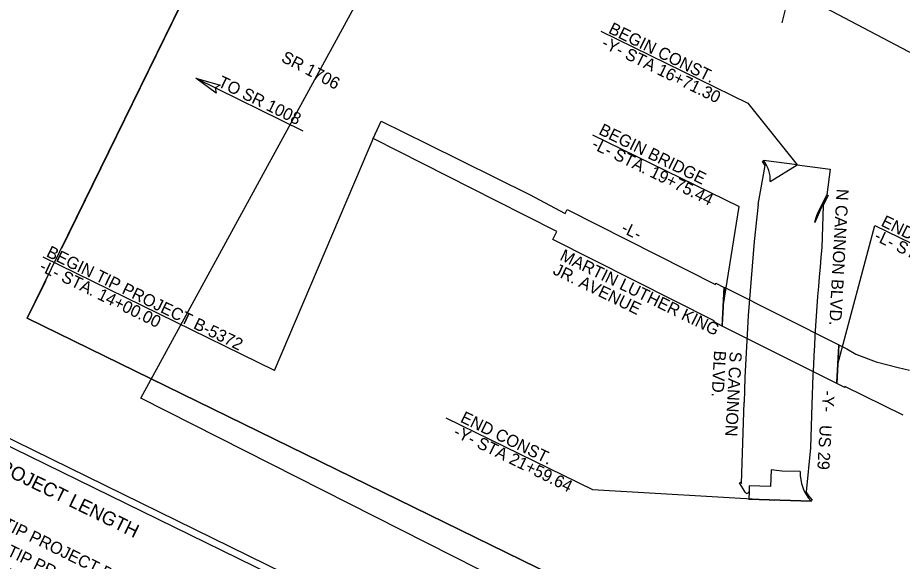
# Model space of a CAD drawing. Extents: x 1517888 to 1526099, y 633375 to 640181.
# Drawn here: x 1519355 to 1520641, y 637793 to 638583 of the extents above; entities that cross this region are included whole.
import ezdxf

# ---------------------------------------------------------------- set-up
doc = ezdxf.new("R2010")
doc.units = 0
for name, color, linetype in [('Prop Shade Heavy', 7, 'Continuous'), ('Prop Shade Light', 7, 'Continuous'), ('Prop Terminator CELL', 7, 'Continuous'), ('Scratch_Level_0', 7, 'Continuous'), ('Sheet Clip Boundary CELL', 7, 'Continuous'), ('Sheet Data Field CELL', 7, 'Continuous'), ('Sheet Title CELL', 7, 'Continuous')]:
    doc.layers.add(name, color=color, linetype=linetype)

msp = doc.modelspace()

# ---------------------------------------------------------------- linework, layer by layer
at = {"layer": 'Prop Shade Heavy'}
msp.add_lwpolyline([(1520545.8, 638051.5), (1520379.2, 638135.1), (1520382.3, 638191.5), (1520548.9, 638107.9)], close=True, dxfattribs=at)
at = {"layer": 'Prop Shade Light'}
for p, q in [((1520437.7, 638374.3), (1520439.3, 638375.5)), ((1520488.1, 638369.2), (1520439.3, 638375.5)), ((1520449.2, 638345), (1520488.1, 638369.2)), ((1520449.2, 638345), (1520488.1, 638369.2)), ((1520488.1, 638369.2), (1520536.2, 638363)), ((1520536.2, 638363), (1520531.4, 638325.7)), ((1520531.4, 638325.7), (1520513.8, 638285.5)), ((1520513.8, 638285.5), (1520531.4, 638325.7)), ((1520517.9, 638298.5), (1520531.4, 638325.7)), ((1520531.4, 638325.7), (1520517.9, 638298.5)), ((1520533.2, 638324.9), (1520525.9, 638310.2)), ((1520531.4, 638325.7), (1520533.2, 638324.9)), ((1520525.9, 638310.2), (1520524.2, 638249.4)), ((1520407.4, 637906.2), (1520411.1, 638024.2)), ((1520450.5, 637926), (1520449.8, 637902.1)), ((1520450.5, 637926), (1520449.8, 637902.1)), ((1520466, 637924.3), (1520450.5, 637926)), ((1520466, 637924.3), (1520450.5, 637926)), ((1520492.8, 637923.5), (1520466, 637924.3)), ((1520492.8, 637923.5), (1520466, 637924.3)), ((1520404.5, 637907.1), (1520406.2, 637908.2)), ((1520412.9, 637893.4), (1520404.5, 637907.1)), ((1520406.2, 637908.2), (1520407.4, 637906.2)), ((1520418.8, 637903), (1520418.5, 637894.8)), ((1520418.8, 637903), (1520418.5, 637894.8)), ((1520449.8, 637902.1), (1520418.8, 637903)), ((1520449.8, 637902.1), (1520418.8, 637903)), ((1520418.5, 637894.8), (1520418.2, 637883.4)), ((1520418.5, 637894.8), (1520418.2, 637883.4)), ((1520508.6, 637880.6), (1520418.2, 637883.4)), ((1520418.2, 637883.4), (1520508.6, 637880.6)), ((1520510.1, 637881.9), (1520508.6, 637880.6))]:
    msp.add_line(p, q, dxfattribs=at)
msp.add_lwpolyline([(1520139, 638272.6), (1520050.8, 638317.1), (1519944.9, 638370.9), (1519871.9, 638407.5), (1519883.7, 638432.9), (1519950.4, 638399.8), (1520099.1, 638326.3), (1520150.9, 638298.7), (1520154, 638304.7), (1520369.5, 638195.5), (1520370.3, 638197.5), (1520382.4, 638191.3), (1520382.2, 638190), (1520379.3, 638136.6), (1520379.2, 638135.1), (1520367.5, 638141), (1520367.7, 638142.6), (1520133.4, 638261.1)], close=True, dxfattribs=at)
for points in [[(1520431.6, 638311.9), (1520441.7, 638368.4)], [(1520642.5, 638005.6), (1520557.7, 638047.2), (1520557.5, 638045.6), (1520545.8, 638051.5), (1520545.9, 638053), (1520548.8, 638106.4), (1520548.9, 638107.9), (1520560.6, 638102), (1520573.8, 638094.4), (1520603.3, 638083.3), (1520635.2, 638074.9), (1520651.8, 638071.1)], [(1520509.6, 638021.1), (1520507.6, 637958), (1520501.5, 637894.1)]]:
    msp.add_lwpolyline(points, dxfattribs=at)
for centre, radius, start, end in [((1520404.3, 638347.3), 43, 29.4394, 38.8524), ((1520404.3, 638347.3), 45, 357.112, 38.8524), ((1520404.3, 638347.3), 45, 357.112, 38.8524), ((1524058.6, 637908.8), 3649.3, 173.6592, 178.1887), ((1520558.2, 638278.5), 45, 153.602, 171.0337), ((1520558.2, 638278.5), 45, 153.602, 171.0337), ((1524058.6, 637908.8), 3550.7, 174.4957, 178.1887), ((1520552.7, 637921.3), 60, 177.876, 222.7136), ((1520552.7, 637921.3), 60, 177.876, 222.7136), ((1520415.5, 637894.9), 3, 210.0392, 358.1887), ((1520552.7, 637921.3), 58, 207.9297, 222.7136)]:
    msp.add_arc(centre, radius, start, end, dxfattribs=at)
at = {"layer": 'Prop Terminator CELL'}
msp.add_lwpolyline([(1519643.7, 638473.8), (1519614, 638495.2), (1519649.4, 638485), (1519642.4, 638481.3)], close=True, dxfattribs=at)
at = {"layer": 'Scratch_Level_0'}
msp.add_lwpolyline([(1519830.7, 639089.6), (1521178.1, 638430.5), (1520716.8, 637487.3), (1519369.3, 638146.3)], close=True, dxfattribs=at)
at = {"layer": 'Sheet Clip Boundary CELL'}
msp.add_lwpolyline([(1519997.2, 638878.2), (1520677.9, 638519.7), (1521000.4, 638385.3), (1521102.7, 638308.6), (1521171, 638278.9), (1521396, 638166), (1521492.2, 638121.5), (1521760.4, 637993.1), (1521455.7, 637316.3), (1521359.7, 637143.3), (1520290, 637647.3), (1519534.4, 638030.1)], close=True, dxfattribs=at)
at = {"layer": 'Sheet Data Field CELL'}
for p, q in [((1520507.8, 638744.4), (1520466, 638575.9)), ((1520203.1, 638563.6), (1520416.4, 638459.2)), ((1519614, 638495.2), (1519770, 638418.9)), ((1520416.4, 638459.2), (1520488.1, 638369.2)), ((1519728.4, 638070.6), (1519876.1, 638416.6)), ((1520190.6, 638413.2), (1520403.9, 638308.9)), ((1520380.8, 638163.3), (1520403.9, 638308.9)), ((1520547.4, 638079.7), (1520601.2, 638281.4)), ((1520601.2, 638281.4), (1520788.6, 638189.7)), ((1519728.4, 638070.6), (1519392.4, 638235)), ((1519977.7, 638001.8), (1520191, 637897.5)), ((1520191, 637897.5), (1520455.9, 637882.2))]:
    msp.add_line(p, q, dxfattribs=at)
at = {"layer": 'Sheet Title CELL'}
for p, q in [((1518493.8, 638387), (1521045, 637139.2)), ((1519100.2, 638079.2), (1519782.9, 637745.3))]:
    msp.add_line(p, q, dxfattribs=at)
for points in [[(1520477.5, 638773.2), (1519830.7, 639089.6), (1519418.9, 638247.6)], [(1519396, 638200.8), (1519369.3, 638146.3), (1520716.8, 637487.3)]]:
    msp.add_lwpolyline(points, dxfattribs=at)

# ---------------------------------------------------------------- texts
at = {"layer": 'Sheet Data Field CELL'}
for s, rotation, p in [('BEGIN CONST.', 333.9377, (1520212.8, 638561.6)), ('-Y- STA 16+71.30', 333.9377, (1520202.7, 638541)), ('SR 1706', 332.5024, (1519737, 638520.3)), ('TO SR 1008', 333.9377, (1519644.9, 638483.9)), ('BEGIN BRIDGE', 333.9377, (1520198.6, 638414.5)), ('-L- STA. 19+75.44', 333.9377, (1520188.5, 638393.9)), ('N CANNON BLVD.', 266.8569, (1520545.8, 638334.8)), ('END BRIDGE', 333.9377, (1520609, 638281.2)), ('-L-', 333.9377, (1520231.2, 638272.1)), ('-L- STA. 21+50.94', 333.9377, (1520599, 638260.5)), ('BEGIN TIP PROJECT B-5372', 333.9377, (1519395.6, 638236.8)), ('MARTIN LUTHER KING ', 333.9377, (1520142.1, 638231.9)), ('-L- STA. 14+00.00', 333.9377, (1519385.6, 638216.2)), ('JR. AVENUE', 333.9377, (1520132, 638211.3)), ('BLVD.', 266.8569, (1520367.6, 638099.7)), ('S CANNON ', 266.8569, (1520390.5, 638098.4)), ('-Y-', 266.8569, (1520525.6, 638041.8)), ('END CONST.', 333.9377, (1519997.5, 637996.3)), ('-Y- STA 21+59.64', 333.9377, (1519987.4, 637975.6)), ('US 29', 266.8569, (1520521.2, 637991.6)), ('LENGTH OF ROADWAY TIP PROJECT B-5372 = 0.191 MILES', 333.9377, (1519091.2, 637959.7)), ('LENGTH OF STRUCTURE TIP PROJECT B-5372 = 0.033 MILES', 333.9377, (1519076.6, 637930.1)), ('TOTAL LENGTH OF TIP PROJECT B-5372 =   0.224 MILES', 333.9377, (1519063, 637901.2))]:
    msp.add_text(s, height=17.5, rotation=rotation, dxfattribs=at).set_placement(p)
at = {"layer": 'Sheet Title CELL'}
msp.add_text('PROJECT LENGTH', height=19.999, rotation=333.9377, dxfattribs=at).set_placement((1519309.1, 637932.2))

doc.saveas('drawing.dxf')
